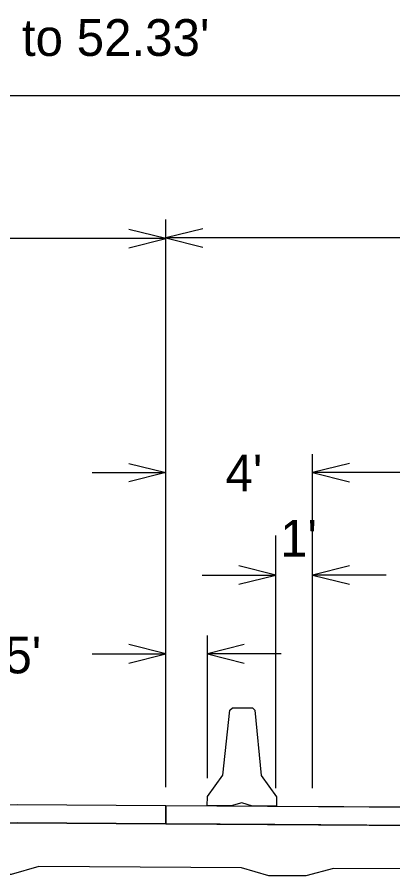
# Model space of a CAD drawing. Extents: x 10133 to 81668, y 7924 to 11018.
# Drawn here: x 11122.5 to 11326.4, y 8330.3 to 8797 of the extents above; entities that cross this region are included whole.
import ezdxf

# ---------------------------------------------------------------- set-up
doc = ezdxf.new("R2010")
doc.units = 0
for name, color, linetype in [('brgConcrete', 7, 'Continuous'), ('brgPreStructureExisting', 7, 'Continuous'), ('dsnStdLineDrawingWt2', 7, 'Continuous')]:
    doc.layers.add(name, color=color, linetype=linetype)

msp = doc.modelspace()

# ---------------------------------------------------------------- linework, layer by layer
at = {"layer": 'brgConcrete'}
for p, q in [((11203.17, 8368.4), (11122.5, 8368.94)), ((11203.19, 8368.4), (11203.15, 8358.61)), ((10492.25, 8349.7), (11122.5, 8359.15)), ((11203.15, 8358.61), (11122.5, 8359.15)), ((11203.17, 8358.61), (11122.5, 8359.15)), ((11203.17, 8363.21), (11203.15, 8358.61)), ((11203.17, 8363.21), (11203.15, 8358.61))]:
    msp.add_line(p, q, dxfattribs=at)
at = {"layer": 'brgPreStructureExisting'}
for p, q in [((11262.25, 8368.01), (11203.17, 8368.4)), ((11561.92, 8366), (11262.25, 8368.01)), ((11262.25, 8358.21), (11203.15, 8358.61)), ((11561.92, 8356.2), (11262.25, 8358.21)), ((11244.17, 8334.61), (11134.17, 8335.34)), ((11404.17, 8333.53), (11294.17, 8334.27))]:
    msp.add_line(p, q, dxfattribs=at)
for points in [[(11263.17, 8368.14), (11250.25, 8368.22), (11244.43, 8369.93), (11238.59, 8368.3), (11225.67, 8368.39), (11225.7, 8373.39), (11234.11, 8385), (11237.97, 8420.39), (11239.36, 8421.63), (11250.19, 8421.56), (11251.56, 8420.3), (11254.95, 8384.86), (11263.2, 8373.14)], [(10762.25, 8363.54), (10492.25, 8359.49), (10492.25, 8349.7), (11122.5, 8359.15), (11203.15, 8358.61), (11203.19, 8368.4), (11122.5, 8368.94)], [(11203.19, 8368.4), (11203.15, 8358.61), (11561.92, 8356.2), (11561.92, 8366)]]:
    msp.add_lwpolyline(points, close=True, dxfattribs=at)
for points in [[(11134.17, 8335.34), (11119.17, 8331.05), (11099.17, 8331.05), (11084.17, 8334.85)], [(11294.17, 8334.27), (11279.17, 8330.27), (11259.17, 8330.27), (11244.17, 8334.61)]]:
    msp.add_lwpolyline(points, dxfattribs=at)
at = {"layer": 'dsnStdLineDrawingWt2'}
for p, q in [((11562.25, 8754.24), (10492.25, 8754.24)), ((11203.17, 8378.4), (11203.17, 8686.98)), ((11203.17, 8676.59), (10492.25, 8676.59)), ((11561.92, 8676.98), (11203.17, 8676.98)), ((11282.85, 8377.87), (11282.85, 8559.4)), ((11163.17, 8549.4), (11203.17, 8549.4)), ((11522.85, 8549.4), (11282.85, 8549.4)), ((11262.85, 8378), (11262.85, 8515.18)), ((11222.85, 8493.75), (11262.85, 8493.75)), ((11322.85, 8493.75), (11282.85, 8493.75)), ((11203.17, 8378.4), (11203.17, 8460.93)), ((11225.7, 8383.39), (11225.7, 8460.93)), ((11262.85, 8378), (11262.85, 8460.93)), ((11163.17, 8450.93), (11203.17, 8450.93)), ((11265.7, 8450.93), (11225.7, 8450.93))]:
    msp.add_line(p, q, dxfattribs=at)
for points in [[(11183.17, 8671.59), (11203.17, 8676.59), (11183.17, 8681.59)], [(11223.17, 8681.98), (11203.17, 8676.98), (11223.17, 8671.98)], [(11183.17, 8554.4), (11203.17, 8549.4), (11183.17, 8544.4)], [(11302.85, 8554.4), (11282.85, 8549.4), (11302.85, 8544.4)], [(11242.85, 8488.75), (11262.85, 8493.75), (11242.85, 8498.75)], [(11302.85, 8498.75), (11282.85, 8493.75), (11302.85, 8488.75)], [(11183.17, 8445.93), (11203.17, 8450.93), (11183.17, 8455.93)], [(11245.7, 8455.93), (11225.7, 8450.93), (11245.7, 8445.93)]]:
    msp.add_lwpolyline(points, dxfattribs=at)

# ---------------------------------------------------------------- texts
for s, p in [("Varies: 59.08' to 52.33'", (10954.92, 8775.9)), ("4'", (11235.57, 8539.24)), ("1'", (11265.2, 8503.75)), ("1.125'", (11063.5, 8440.32))]:
    msp.add_text(s, height=20, dxfattribs=at).set_placement(p)

doc.saveas('drawing.dxf')
